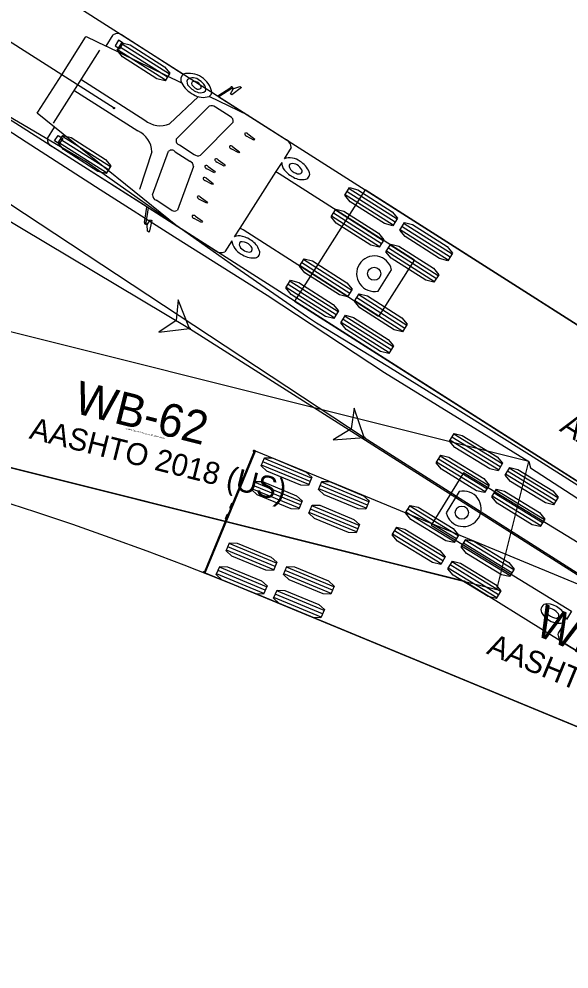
# Model space of a CAD drawing. Extents: x 973688 to 979179, y 703586 to 707602.
# Drawn here: x 978624.6 to 978660.1, y 703870.2 to 703931.4 of the extents above; entities that cross this region are included whole.
import ezdxf

# ---------------------------------------------------------------- set-up
doc = ezdxf.new("R2010")
doc.units = 0
doc.layers.add('Radius Check', color=7, linetype='Continuous')

msp = doc.modelspace()

# ---------------------------------------------------------------- linework, layer by layer
at = {"layer": 'Radius Check'}
for p, q in [((978630.758, 703925.703), (978571.419, 703963.488)), ((978635.126, 703927.316), (978630.246, 703929.692)), ((978631.054, 703930.068), (978630.833, 703929.719)), ((978630.833, 703929.719), (978631.133, 703929.528)), ((978630.99, 703929.482), (978634.083, 703927.513)), ((978631.355, 703929.876), (978631.054, 703930.068)), ((978631.114, 703929.675), (978634.206, 703927.706)), ((978631.133, 703929.528), (978631.355, 703929.876)), ((978631.237, 703929.869), (978634.329, 703927.899)), ((978629.813, 703929.431), (978626.825, 703924.738)), ((978628.621, 703927.558), (978632.747, 703924.931)), ((978609.951, 703926.816), (978635.631, 703911.487)), ((978628.173, 703926.855), (978632.299, 703924.227)), ((978634.345, 703924.687), (978636.214, 703926.437)), ((978639.418, 703925.227), (978636.895, 703926.455)), ((978637.521, 703926.435), (978637.436, 703926.489)), ((978638.451, 703926.921), (978638.465, 703926.945)), ((978638.465, 703926.945), (978638.491, 703926.955)), ((978636.89, 703925.821), (978634.769, 703923.691)), ((978638.244, 703925.155), (978637.291, 703925.762)), ((978636.33, 703922.658), (978638.45, 703924.789)), ((978634.853, 703918.057), (978626.927, 703924.479)), ((978639.388, 703924.032), (978639.83, 703923.704)), ((978626.929, 703923.588), (978627.15, 703923.936)), ((978627.229, 703923.397), (978626.929, 703923.588)), ((978627.15, 703923.936), (978627.45, 703923.745)), ((978627.186, 703923.507), (978630.279, 703921.538)), ((978627.45, 703923.745), (978627.229, 703923.397)), ((978627.309, 703923.7), (978630.402, 703921.731)), ((978627.432, 703923.894), (978630.525, 703921.924)), ((978639.782, 703923.628), (978639.297, 703923.89)), ((978639.83, 703923.704), (978639.782, 703923.628)), ((978633.196, 703922.882), (978632.405, 703920.461)), ((978633.245, 703920.097), (978634.278, 703922.92)), ((978634.697, 703922.888), (978635.65, 703922.281)), ((978634.975, 703923.325), (978635.929, 703922.718)), ((978638.803, 703922.808), (978638.318, 703923.07)), ((978638.408, 703923.212), (978638.851, 703922.884)), ((978638.851, 703922.884), (978638.803, 703922.808)), ((978637.867, 703921.961), (978637.382, 703922.223)), ((978637.472, 703922.365), (978637.915, 703922.036)), ((978635.874, 703921.942), (978634.84, 703919.119)), ((978637.227, 703921.53), (978636.742, 703921.793)), ((978636.833, 703921.935), (978637.275, 703921.606)), ((978637.275, 703921.606), (978637.227, 703921.53)), ((978637.915, 703922.036), (978637.867, 703921.961)), ((978641.199, 703921.621), (978638.873, 703917.969)), ((978637.108, 703920.769), (978636.623, 703921.031)), ((978636.714, 703921.173), (978637.156, 703920.845)), ((978637.156, 703920.845), (978637.108, 703920.769)), ((978645.791, 703920.33), (978648.883, 703918.36)), ((978645.914, 703920.523), (978649.007, 703918.553)), ((978634.422, 703919.151), (978633.468, 703919.759)), ((978636.736, 703919.562), (978636.23, 703919.837)), ((978636.32, 703919.979), (978636.784, 703919.638)), ((978645.667, 703920.136), (978648.76, 703918.167)), ((978623.986, 703919.57), (978646.892, 703904.463)), ((978632.955, 703919.265), (978632.871, 703919.319)), ((978636.784, 703919.638), (978636.736, 703919.562)), ((978645.027, 703919.131), (978648.12, 703917.162)), ((978636.407, 703918.328), (978635.923, 703918.59)), ((978636.013, 703918.732), (978636.456, 703918.404)), ((978644.781, 703918.744), (978647.874, 703916.775)), ((978644.904, 703918.938), (978647.997, 703916.968)), ((978632.909, 703918.217), (978632.893, 703918.194)), ((978632.893, 703918.194), (978632.895, 703918.167)), ((978636.456, 703918.404), (978636.407, 703918.328)), ((978649.21, 703917.88), (978652.303, 703915.911)), ((978649.333, 703918.074), (978652.426, 703916.104)), ((978649.456, 703918.267), (978652.549, 703916.297)), ((978648.447, 703916.682), (978651.54, 703914.712)), ((978648.57, 703916.875), (978651.663, 703914.906)), ((978648.324, 703916.489), (978651.417, 703914.519)), ((978642.749, 703915.553), (978645.842, 703913.584)), ((978642.872, 703915.746), (978645.965, 703913.777)), ((978642.995, 703915.94), (978646.088, 703913.97)), ((978647.786, 703913.908), (978648.654, 703915.272)), ((978641.863, 703914.161), (978644.956, 703912.192)), ((978641.986, 703914.355), (978645.079, 703912.385)), ((978642.109, 703914.548), (978645.202, 703912.579)), ((978646.538, 703913.684), (978649.631, 703911.714)), ((978646.292, 703913.297), (978649.385, 703911.328)), ((978646.415, 703913.491), (978649.508, 703911.521)), ((978645.406, 703911.905), (978648.498, 703909.936)), ((978645.529, 703912.099), (978648.622, 703910.129)), ((978645.652, 703912.292), (978648.745, 703910.323)), ((978635.631, 703911.487), (978670.676, 703889.228)), ((978646.892, 703904.463), (978700.816, 703870.201)), ((978655.664, 703902.566), (978652.536, 703904.479)), ((978655.783, 703902.761), (978652.656, 703904.675)), ((978655.544, 703902.37), (978652.417, 703904.284)), ((978636.632, 703895.737), (978639.878, 703903.592)), ((978654.922, 703901.354), (978651.795, 703903.267)), ((978643.32, 703901.426), (978640.27, 703902.686)), ((978643.408, 703901.638), (978640.358, 703902.898)), ((978643.495, 703901.85), (978640.445, 703903.11)), ((978654.683, 703900.963), (978651.555, 703902.876)), ((978654.803, 703901.158), (978651.675, 703903.072)), ((978659.127, 703900.178), (978655.999, 703902.092)), ((978659.246, 703900.373), (978656.119, 703902.287)), ((978659.366, 703900.569), (978656.238, 703902.483)), ((978642.778, 703900.113), (978639.728, 703901.373)), ((978642.865, 703900.325), (978639.815, 703901.585)), ((978647.105, 703900.11), (978644.055, 703901.37)), ((978647.192, 703900.322), (978644.142, 703901.582)), ((978642.69, 703899.901), (978639.64, 703901.161)), ((978647.017, 703899.898), (978643.967, 703901.159)), ((978653.018, 703900.98), (978652.174, 703899.601)), ((978658.266, 703898.77), (978655.138, 703900.684)), ((978658.385, 703898.966), (978655.258, 703900.88)), ((978658.505, 703899.161), (978655.377, 703901.075)), ((978638.291, 703899.937), (978638.392, 703900.182)), ((978638.189, 703899.691), (978638.255, 703899.665)), ((978646.387, 703898.373), (978643.337, 703899.634)), ((978646.474, 703898.585), (978643.425, 703899.845)), ((978646.562, 703898.797), (978643.512, 703900.057)), ((978652.708, 703897.736), (978649.581, 703899.649)), ((978652.828, 703897.931), (978649.7, 703899.845)), ((978652.948, 703898.126), (978649.82, 703900.04)), ((978637.987, 703899.201), (978638.088, 703899.446)), ((978651.847, 703896.328), (978648.72, 703898.242)), ((978651.967, 703896.524), (978648.839, 703898.437)), ((978652.086, 703896.719), (978648.959, 703898.633)), ((978641.229, 703896.366), (978638.179, 703897.626)), ((978656.411, 703895.739), (978653.283, 703897.653)), ((978656.53, 703895.934), (978653.403, 703897.848)), ((978641.054, 703895.942), (978638.004, 703897.203)), ((978641.142, 703896.154), (978638.092, 703897.415)), ((978656.291, 703895.543), (978653.163, 703897.457)), ((978655.669, 703894.527), (978652.541, 703896.441)), ((978640.512, 703894.629), (978637.462, 703895.89)), ((978640.599, 703894.841), (978637.549, 703896.101)), ((978644.838, 703894.627), (978641.789, 703895.887)), ((978644.926, 703894.838), (978641.876, 703896.099)), ((978655.43, 703894.136), (978652.302, 703896.05)), ((978655.549, 703894.331), (978652.422, 703896.245)), ((978640.424, 703894.417), (978637.374, 703895.678)), ((978644.751, 703894.415), (978641.701, 703895.675)), ((978644.296, 703893.313), (978641.246, 703894.574)), ((978644.121, 703892.89), (978641.071, 703894.15)), ((978644.208, 703893.102), (978641.158, 703894.362))]:
    msp.add_line(p, q, dxfattribs=at)
for points in [[(978583.822, 703960.606), (978614.448, 703941.127), (978691.664, 703891.958), (978687.099, 703884.789), (978686.971, 703884.87), (978686.971, 703884.87)], [(978686.971, 703884.87), (978616.171, 703929.944), (978611.831, 703932.669), (978607.641, 703935.235), (978605.619, 703936.438), (978603.646, 703937.583), (978601.717, 703938.667), (978599.827, 703939.689), (978597.969, 703940.651), (978596.137, 703941.553), (978594.332, 703942.393), (978592.555, 703943.167), (978590.807, 703943.875), (978589.091, 703944.516)], [(978611.601, 703932.166), (978612.913, 703931.399), (978615.483, 703929.76), (978625.102, 703923.517), (978629.874, 703920.448), (978634.654, 703917.407), (978640.639, 703913.649), (978648.204, 703908.645), (978653.191, 703905.591), (978657.499, 703902.922), (978657.61, 703902.501), (978667.071, 703896.391)], [(978612.023, 703932.244), (978613.385, 703931.436), (978614.729, 703930.604), (978629.02, 703922.223), (978633.855, 703918.79), (978638.609, 703915.45), (978643.235, 703912.235), (978643.808, 703911.858), (978648.41, 703909.054), (978652.939, 703906.25), (978657.538, 703903.367), (978666.714, 703897.544)], [(978626.463, 703923.749), (978626.923, 703924.472), (978626.926, 703924.48), (978625.812, 703925.383), (978625.846, 703925.436), (978627.384, 703927.852), (978628.922, 703930.267), (978628.956, 703930.32), (978630.245, 703929.692), (978630.251, 703929.699), (978630.711, 703930.422)], [(978631.309, 703930.391), (978635.226, 703927.896)], [(978637.07, 703926.722), (978637.429, 703926.493), (978637.444, 703926.495), (978638.28, 703927.036)], [(978638.417, 703927.001), (978638.49, 703926.955), (978638.493, 703926.956), (978638.864, 703927.096), (978638.867, 703927.096), (978638.967, 703927.033), (978638.967, 703927.031), (978638.364, 703926.562), (978638.277, 703926.617), (978638.45, 703926.92), (978638.45, 703926.921), (978638.382, 703926.963), (978638.382, 703926.964), (978638.381, 703926.964), (978638.344, 703926.973), (978638.343, 703926.973), (978637.521, 703926.435), (978641.887, 703923.655)], [(978632.732, 703918.323), (978632.869, 703919.309), (978632.864, 703919.324), (978626.743, 703923.221)], [(978642.173, 703923.151), (978641.719, 703922.438)], [(978641.568, 703922.2), (978641.2, 703921.622), (978641.4, 703921.493), (978650.14, 703915.928), (978648.977, 703914.101), (978647.814, 703912.275), (978639.074, 703917.841), (978638.873, 703917.968), (978638.505, 703917.39)], [(978691.593, 703891.978), (978691.604, 703891.996), (978691.545, 703892.034), (978686.765, 703895.078), (978646.958, 703920.426), (978644.676, 703916.841), (978642.393, 703913.256), (978682.199, 703887.909), (978686.98, 703884.865), (978687.04, 703884.827), (978687.051, 703884.845)], [(978637.321, 703916.485), (978632.955, 703919.265), (978632.816, 703918.292), (978632.816, 703918.292), (978632.84, 703918.262), (978632.84, 703918.262), (978632.841, 703918.261), (978632.908, 703918.218), (978632.909, 703918.218), (978633.11, 703918.503), (978633.197, 703918.448), (978633.027, 703917.703), (978633.026, 703917.702), (978632.926, 703917.766), (978632.925, 703917.769), (978632.895, 703918.164), (978632.894, 703918.167), (978632.821, 703918.214)], [(978638.353, 703917.152), (978637.899, 703916.439)], [(978608.945, 703906.328), (978608.94, 703906.306), (978655.437, 703894.676), (978656.468, 703898.799), (978657.499, 703902.922), (978611.003, 703914.552), (978610.997, 703914.531)], [(978635.631, 703911.487), (978634.892, 703913.346), (978634.772, 703912), (978633.644, 703911.255), (978635.631, 703911.487)], [(978672, 703883.728), (978659.075, 703891.638), (978653.323, 703895.201), (978612.628, 703905.383), (978610.241, 703905.946), (978607.905, 703906.446), (978605.569, 703906.893), (978603.23, 703907.286), (978600.908, 703907.62), (978598.605, 703907.891), (978596.325, 703908.099), (978594.071, 703908.241), (978591.847, 703908.317), (978589.656, 703908.325), (978587.502, 703908.265)], [(978646.892, 703904.463), (978646.238, 703906.353), (978646.057, 703905.014), (978644.897, 703904.321), (978646.892, 703904.463)], [(978674.364, 703880.144), (978639.973, 703894.355), (978637.617, 703895.309), (978635.274, 703896.228), (978632.901, 703897.129), (978630.507, 703898.006), (978628.112, 703898.85), (978625.716, 703899.657), (978623.32, 703900.428), (978620.926, 703901.16), (978618.534, 703901.85), (978616.146, 703902.496), (978613.763, 703903.098), (978611.388, 703903.651), (978609.022, 703904.155), (978606.667, 703904.607), (978604.326, 703905.005), (978602.002, 703905.347), (978599.697, 703905.632), (978597.415, 703905.857), (978595.159, 703906.022), (978592.933, 703906.125), (978590.741, 703906.165), (978588.617, 703906.142)], [(978636.575, 703895.784), (978636.567, 703895.764), (978636.632, 703895.737), (978641.869, 703893.572), (978685.484, 703875.549), (978687.107, 703879.477), (978688.73, 703883.405), (978645.116, 703901.428), (978639.878, 703903.592), (978639.812, 703903.619), (978639.804, 703903.599)], [(978639.795, 703903.576), (978639.794, 703903.575), (978638.406, 703900.216), (978638.392, 703900.183), (978638.328, 703900.209), (978638.327, 703900.208), (978638.225, 703899.961)], [(978662.659, 703897.201), (978662.33, 703896.664), (978653.289, 703902.196), (978651.215, 703898.807), (978660.256, 703893.274), (978659.927, 703892.736)], [(978638.024, 703899.475), (978637.922, 703899.229), (978637.922, 703899.227), (978637.986, 703899.201), (978637.973, 703899.167), (978636.584, 703895.808), (978636.584, 703895.807)], [(978638.288, 703899.931), (978638.089, 703899.449)], [(978659.793, 703892.517), (978659.388, 703891.855)], [(978659.681, 703891.266), (978664.016, 703888.614), (978663.335, 703888.183), (978663.335, 703888.183)]]:
    msp.add_lwpolyline(points, dxfattribs=at)
for points in [[(978630.96, 703929.434), (978631.267, 703929.917), (978631.793, 703929.786), (978634.02, 703928.368), (978634.36, 703927.947), (978634.053, 703927.465), (978633.527, 703927.595), (978631.3, 703929.013)], [(978627.155, 703923.459), (978627.463, 703923.942), (978627.988, 703923.811), (978630.215, 703922.393), (978630.555, 703921.972), (978630.248, 703921.49), (978629.723, 703921.62), (978627.496, 703923.038)], [(978645.637, 703920.088), (978645.944, 703920.571), (978646.47, 703920.44), (978648.697, 703919.022), (978649.037, 703918.601), (978648.73, 703918.119), (978648.204, 703918.249), (978645.977, 703919.667)], [(978644.751, 703918.696), (978645.058, 703919.179), (978645.583, 703919.049), (978647.81, 703917.631), (978648.151, 703917.21), (978647.844, 703916.727), (978647.318, 703916.857), (978645.091, 703918.275)], [(978649.18, 703917.832), (978649.487, 703918.315), (978650.012, 703918.185), (978652.239, 703916.767), (978652.58, 703916.345), (978652.273, 703915.863), (978651.747, 703915.993), (978649.52, 703917.411)], [(978648.293, 703916.441), (978648.601, 703916.923), (978649.126, 703916.793), (978651.353, 703915.375), (978651.694, 703914.954), (978651.386, 703914.471), (978650.861, 703914.602), (978648.634, 703916.019)], [(978642.719, 703915.505), (978643.026, 703915.988), (978643.551, 703915.857), (978645.778, 703914.439), (978646.119, 703914.018), (978645.811, 703913.536), (978645.286, 703913.666), (978643.059, 703915.084)], [(978641.832, 703914.113), (978642.14, 703914.596), (978642.665, 703914.466), (978644.892, 703913.048), (978645.232, 703912.626), (978644.925, 703912.144), (978644.4, 703912.274), (978642.173, 703913.692)], [(978646.261, 703913.249), (978646.569, 703913.732), (978647.094, 703913.601), (978649.321, 703912.183), (978649.661, 703911.762), (978649.354, 703911.28), (978648.829, 703911.41), (978646.602, 703912.828)], [(978635.631, 703911.487), (978634.892, 703913.346), (978634.772, 703912), (978633.644, 703911.255)], [(978645.375, 703911.858), (978645.682, 703912.34), (978646.208, 703912.21), (978648.435, 703910.792), (978648.775, 703910.371), (978648.468, 703909.888), (978647.942, 703910.018), (978645.716, 703911.436)], [(978646.892, 703904.463), (978646.238, 703906.353), (978646.057, 703905.014), (978644.897, 703904.321)], [(978655.813, 703902.809), (978655.515, 703902.322), (978654.987, 703902.442), (978652.735, 703903.82), (978652.387, 703904.235), (978652.686, 703904.723), (978653.213, 703904.602), (978655.465, 703903.224)], [(978643.517, 703901.902), (978643.299, 703901.373), (978642.806, 703901.391), (978640.61, 703902.298), (978640.249, 703902.634), (978640.467, 703903.162), (978640.96, 703903.145), (978643.156, 703902.238)], [(978654.952, 703901.402), (978654.653, 703900.914), (978654.126, 703901.035), (978651.874, 703902.413), (978651.526, 703902.828), (978651.824, 703903.316), (978652.352, 703903.195), (978654.604, 703901.817)], [(978659.396, 703900.617), (978659.097, 703900.129), (978658.569, 703900.25), (978656.317, 703901.628), (978655.97, 703902.043), (978656.268, 703902.531), (978656.796, 703902.41), (978659.048, 703901.032)], [(978642.887, 703900.377), (978642.668, 703899.849), (978642.176, 703899.866), (978639.98, 703900.773), (978639.619, 703901.109), (978639.837, 703901.637), (978640.33, 703901.62), (978642.526, 703900.713)], [(978647.214, 703900.374), (978646.995, 703899.846), (978646.503, 703899.863), (978644.307, 703900.77), (978643.945, 703901.106), (978644.164, 703901.635), (978644.657, 703901.618), (978646.853, 703900.71)], [(978658.534, 703899.21), (978658.236, 703898.722), (978657.708, 703898.843), (978655.456, 703900.221), (978655.108, 703900.636), (978655.407, 703901.124), (978655.935, 703901.003), (978658.187, 703899.625)], [(978646.584, 703898.849), (978646.365, 703898.321), (978645.872, 703898.338), (978643.676, 703899.245), (978643.315, 703899.581), (978643.534, 703900.11), (978644.027, 703900.093), (978646.222, 703899.185)], [(978652.977, 703898.175), (978652.679, 703897.687), (978652.151, 703897.808), (978649.899, 703899.186), (978649.551, 703899.601), (978649.85, 703900.089), (978650.377, 703899.968), (978652.629, 703898.59)], [(978652.116, 703896.768), (978651.818, 703896.28), (978651.29, 703896.401), (978649.038, 703897.778), (978648.69, 703898.193), (978648.988, 703898.681), (978649.516, 703898.56), (978651.768, 703897.182)], [(978641.251, 703896.419), (978641.032, 703895.89), (978640.54, 703895.907), (978638.344, 703896.814), (978637.983, 703897.15), (978638.201, 703897.679), (978638.694, 703897.662), (978640.89, 703896.754)], [(978656.56, 703895.983), (978656.261, 703895.495), (978655.733, 703895.616), (978653.482, 703896.994), (978653.134, 703897.409), (978653.432, 703897.897), (978653.96, 703897.776), (978656.212, 703896.398)], [(978655.699, 703894.575), (978655.4, 703894.087), (978654.872, 703894.208), (978652.62, 703895.586), (978652.272, 703896.001), (978652.571, 703896.489), (978653.099, 703896.368), (978655.351, 703894.99)], [(978640.621, 703894.894), (978640.402, 703894.365), (978639.91, 703894.382), (978637.714, 703895.29), (978637.352, 703895.625), (978637.571, 703896.154), (978638.064, 703896.137), (978640.26, 703895.229)], [(978644.948, 703894.891), (978644.729, 703894.362), (978644.236, 703894.379), (978642.041, 703895.287), (978641.679, 703895.623), (978641.898, 703896.151), (978642.391, 703896.134), (978644.587, 703895.227)], [(978644.318, 703893.366), (978644.099, 703892.837), (978643.606, 703892.854), (978641.41, 703893.762), (978641.049, 703894.098), (978641.268, 703894.626), (978641.761, 703894.609), (978643.956, 703893.702)]]:
    msp.add_lwpolyline(points, close=True, dxfattribs=at)
for centre, radius in [((978630.758, 703925.703), 0.0417), ((978647.534, 703915.021), 0.424), ((978635.631, 703911.487), 0.0417), ((978635.631, 703911.487), 0.0417), ((978646.892, 703904.463), 0.0417), ((978646.892, 703904.463), 0.0417), ((978639.768, 703903.601), 0.0266), ((978653.181, 703899.621), 0.424), ((978636.548, 703895.808), 0.0266)]:
    msp.add_circle(centre, radius, dxfattribs=at)
for centre, radius, start, end in [((978630.99, 703930.024), 0.486, 49.09835, 125.04946), ((978635.486, 703927.542), 0.425, 125.57536, 212.11172), ((978635.571, 703926.406), 1.53, 12.00516, 103.0142), ((978635.845, 703927.016), 0.634, 48.09628, 124.098), ((978636.638, 703928.101), 1.704, 207.43311, 243.34117), ((978635.823, 703927.39), 0.366, 155.56476, 228.04575), ((978636.507, 703927.86), 1.189, 218.64362, 254.53294), ((978635.91, 703927.29), 0.158, 152.48364, 213.99639), ((978635.926, 703927.203), 0.223, 64.74732, 134.34981), ((978636.275, 703927.494), 0.575, 210.58754, 247.15787), ((978635.851, 703926.84), 0.589, 30.26795, 73.25066), ((978635.734, 703926.608), 1.03, 30.33607, 58.72258), ((978636.212, 703927.054), 0.17, 335.18148, 29.24582), ((978636.364, 703926.946), 0.317, 333.36262, 34.95502), ((978638.33, 703927.019), 0.0522, 56.39502, 161.24963), ((978638.316, 703926.964), 0.108, 20.48875, 66.67125), ((978636.506, 703927.523), 1.136, 236.21696, 290.01953), ((978636.196, 703927.183), 0.263, 236.44733, 310.34925), ((978636.346, 703927.126), 0.44, 249.30666, 313.11951), ((978636.722, 703926.756), 0.347, 299.83963, 354.65021), ((978637.042, 703925.466), 0.387, 49.94761, 113.17957), ((978633.74, 703926.077), 1.517, 229.09247, 293.51988), ((978638.123, 703924.845), 0.332, 350.16902, 68.59102), ((978631.68, 703922.842), 1.517, 1.50496, 65.93238), ((978639.262, 703923.938), 0.157, 36.85678, 123.96644), ((978639.358, 703924.064), 0.184, 178.66722, 250.55924), ((978626.941, 703923.665), 0.486, 169.97538, 245.92649), ((978635.054, 703923.61), 0.296, 164.23118, 254.52886), ((978641.554, 703923.133), 0.619, 1.67273, 57.51444), ((978634.471, 703922.696), 0.296, 40.49599, 130.79366), ((978638.283, 703923.118), 0.157, 36.85678, 123.96644), ((978638.379, 703923.244), 0.184, 178.66722, 250.55924), ((978635.487, 703921.93), 0.387, 1.84772, 65.07478), ((978636.177, 703923.014), 0.387, 229.95006, 293.17712), ((978637.347, 703922.271), 0.157, 36.85678, 123.96644), ((978637.443, 703922.396), 0.184, 178.66722, 250.55924), ((978642.297, 703922.19), 0.729, 179.18994, 221.70393), ((978642.068, 703921.357), 1.136, 53.09119, 107.88248), ((978642.212, 703921.953), 0.169, 108.95938, 209.07809), ((978642.271, 703921.603), 0.522, 55.34293, 102.50706), ((978642.033, 703921.044), 1.416, 22.51641, 59.58427), ((978636.775, 703921.946), 0.157, 171.0584, 258.16806), ((978636.707, 703921.84), 0.157, 36.85678, 123.96644), ((978643.099, 703922.791), 1.73, 218.88727, 243.68578), ((978642.722, 703922.193), 0.732, 206.10416, 252.3386), ((978642.658, 703921.822), 0.362, 244.17488, 293.21586), ((978642.262, 703921.443), 0.664, 24.38688, 62.60859), ((978642.714, 703921.638), 0.172, 300.06022, 27.21082), ((978643.026, 703921.445), 0.346, 287.10667, 24.11972), ((978636.655, 703921.185), 0.157, 171.0584, 258.16806), ((978636.582, 703921.044), 0.184, 44.4656, 116.35762), ((978642.896, 703922.226), 1.136, 240.22771, 281.74846), ((978633.631, 703920.109), 0.387, 181.84527, 245.07724), ((978636.283, 703919.978), 0.157, 171.0584, 258.16806), ((978636.21, 703919.837), 0.184, 44.4656, 116.35762), ((978634.651, 703919.392), 0.332, 226.43382, 304.85583), ((978635.955, 703918.744), 0.157, 171.0584, 258.16806), ((978635.882, 703918.603), 0.184, 44.4656, 116.35762), ((978632.768, 703918.285), 0.0522, 133.77521, 238.62982), ((978632.813, 703918.321), 0.108, 228.35359, 274.53609), ((978638.822, 703916.734), 0.729, 73.32091, 115.8349), ((978638.617, 703915.752), 1.73, 51.33906, 76.13757), ((978639.48, 703917.293), 1.136, 187.14236, 241.93365), ((978639.001, 703916.91), 0.169, 85.94675, 186.06546), ((978639.343, 703917.005), 0.522, 192.51779, 239.68191), ((978638.999, 703916.347), 0.732, 42.68624, 88.92068), ((978639.308, 703916.562), 0.362, 1.80898, 50.84996), ((978639.043, 703916.175), 1.136, 13.27638, 54.79713), ((978637.654, 703917.007), 0.619, 237.5104, 293.35211), ((978639.749, 703917.457), 1.416, 235.44057, 272.50843), ((978639.485, 703917.081), 0.664, 232.41625, 270.63797), ((978639.499, 703916.589), 0.172, 267.81402, 354.96462), ((978639.806, 703916.388), 0.346, 270.90512, 7.91817), ((978647.538, 703915.024), 1.143, 12.51242, 282.51242), ((978639.768, 703903.601), 0.0363, 356.62495, 317.7863), ((978653.285, 703899.869), 1.143, 193.5376, 103.5376), ((978638.056, 703899.462), 0.0354, 161.83904, 334.0245), ((978638.056, 703899.462), 0.0352, 338.52182, 157.52223), ((978638.257, 703899.948), 0.0352, 157.57277, 336.57318), ((978638.258, 703899.949), 0.0353, 340.88368, 159.23333), ((978634.706, 703896.557), 2.022, 337.5475, 338.23126), ((978658.664, 703893.358), 0.383, 89.00838, 208.06682), ((978658.841, 703893.3), 0.228, 159.34046, 221.2353), ((978658.813, 703893.194), 0.262, 68.22044, 134.74563), ((978658.627, 703892.398), 1.344, 14.57304, 88.12784), ((978658.692, 703892.586), 0.879, 41.07446, 75.6697), ((978659.502, 703893.829), 1.344, 208.94736, 282.50216), ((978659.357, 703893.667), 0.86, 217.00224, 256.97163), ((978659.239, 703893.11), 0.29, 254.73331, 310.89334), ((978659.197, 703892.974), 0.247, 340.2549, 50.134), ((978659.953, 703891.768), 0.571, 171.23063, 241.62222)]:
    msp.add_arc(centre, radius, start, end, dxfattribs=at)
for centre, major_axis, start_param, end_param in [((978638.348, 703927.019), (-0.066, 0.042), 0.569648, 1.840391), ((978638.348, 703927.019), (-0.066, 0.042), 2.398717, 3.668019), ((978632.776, 703918.268), (0.066, -0.042), 1.301202, 2.571945), ((978632.776, 703918.268), (-0.066, 0.042), 2.615166, 3.884468)]:
    msp.add_ellipse(centre, major_axis=major_axis, ratio=0.544872, start_param=start_param, end_param=end_param, dxfattribs=at)

# ---------------------------------------------------------------- texts
for s, height, rotation, p in [('WB-62', 2.125, 345.95617, (978628.073, 703906.077)), ('AASHTO 2018 (US)', 1.41667, 345.95617, (978625.232, 703904.414)), ('AASHTO 2018 (US)', 1.41667, 327.51242, (978659.418, 703904.926)), ('(c) 2020 Transoft Solutions, Inc. All rights reserved.', 0.085, 345.95617, (978631.487, 703905.004)), ('WB-67', 2.125, 337.5475, (978657.771, 703891.784)), ('AASHTO 2018 (US)', 1.41667, 337.5475, (978654.717, 703890.555))]:
    msp.add_text(s, height=height, rotation=rotation, dxfattribs=at).set_placement(p)

doc.saveas('drawing.dxf')
